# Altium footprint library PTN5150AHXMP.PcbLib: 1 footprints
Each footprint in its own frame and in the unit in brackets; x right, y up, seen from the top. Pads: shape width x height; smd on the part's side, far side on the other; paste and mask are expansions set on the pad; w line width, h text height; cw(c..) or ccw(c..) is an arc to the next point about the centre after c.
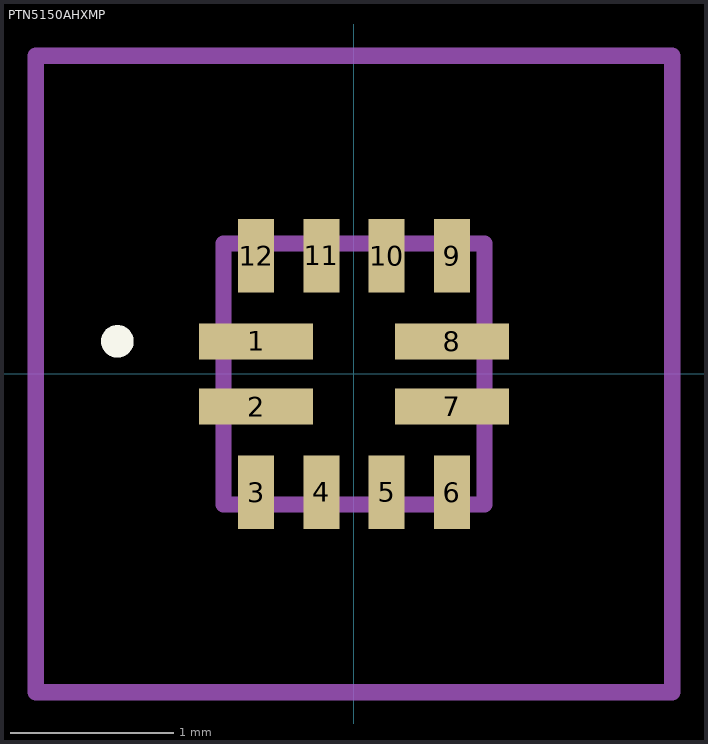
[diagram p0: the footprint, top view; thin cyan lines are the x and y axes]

## PTN5150AHXMP [mm]
pads (12):
  rect 0.7x0.22 smd: 1(-0.6,0.2) 2(-0.6,-0.2) 7(0.6,-0.2) 8(0.6,0.2)
  rect 0.22x0.45 smd: 3(-0.6,-0.725) 4(-0.2,-0.725) 5(0.2,-0.725) 6(0.6,-0.725) 9(0.6,0.725) 10(0.2,0.725) 11(-0.2,0.725) 12(-0.6,0.725)
Top Overlay:
  lines w0.1: -1.5,0.2 cw(c-1.45,0.2) -1.4,0.2 ; -1.5,0.2 -1.5,0.2 ; -1.5,0.2 ccw(c-1.45,0.2) -1.4,0.2 ; -1.4,0.2 -1.4,0.2
Mechanical 15:
  lines w0.1: -0.8,-0.8 0.8,-0.8 0.8,0.8 -0.8,0.8 -0.8,-0.8
Mechanical 20:
  lines w0.1: -1.95,-1.95 1.95,-1.95 1.95,1.95 -1.95,1.95 -1.95,-1.95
